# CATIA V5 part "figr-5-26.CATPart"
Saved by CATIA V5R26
Part number: Part1
Bounding box of the stored display mesh (mm): x -75 to 75, y -100 to 100, z 0 to 53
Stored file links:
  D:\_Deepak\CATIA\CATIA V5-6R2016_Deepak\Resources\Part files\Partfiles\c05_catia_v5_6r2016_prt\figr-5-26.CATPart
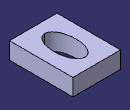
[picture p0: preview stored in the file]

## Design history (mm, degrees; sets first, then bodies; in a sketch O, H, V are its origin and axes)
Body1 (main body)
  Sketch1 on xy-plane, origin (0, 0, 0), H (1, 0, 0), V (0, 1, 0)
    line L1 (-75, 100) -> (75, 100)
    line L2 (75, 100) -> (75, -100)
    line L3 (75, -100) -> (-75, -100)
    line L4 (-75, -100) -> (-75, 100)
    axis line L5 (75, -100) -> (-75, 100)
    length L3 = 150
    length L2 = 200
    horizontal: L1 H, L3 H
    vertical: L2 V, L4 V
    midpoint: L5 O
  Pad1: profile Sketch1, direction (0, 0, 1), length 53
  Sketch2 on face of Pad1, origin (0, 0, 53), H (1, 0, 0), V (0, 1, 0)
    ellipse A1 centre (0, 0) semi-axes 63.781, 34.5424 rotation 270
    point P1 (0, -63.781)
    point P2 (34.5424, 0)
    coincidence: P1 V, P2 H, A1 P1, A1 P2
  Pocket1: profile Sketch2, direction (0, 0, -1), through (limit type 3)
